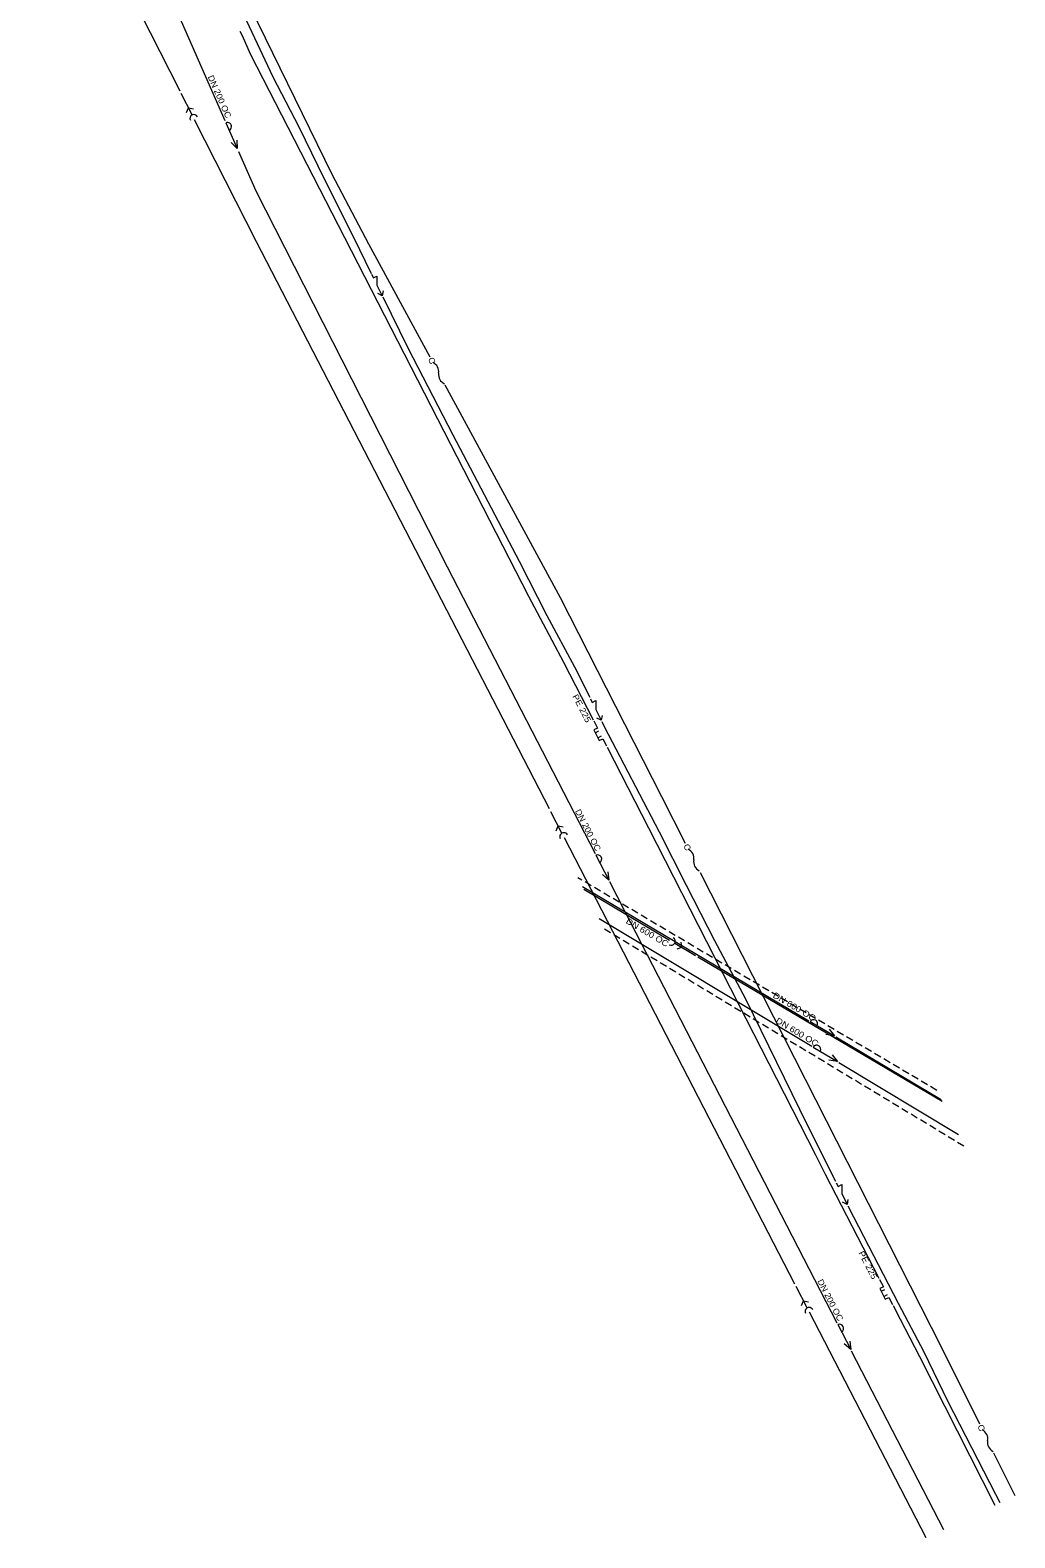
# Model space of a CAD drawing. Extents: x -601552 to -601367, y -1161450 to -1160710.
# Drawn here: x -601543.1 to -601420.6, y -1161449.9 to -1161262.3 of the extents above; entities that cross this region are included whole.
import ezdxf
from ezdxf.enums import TextEntityAlignment as Align

# ---------------------------------------------------------------- set-up
doc = ezdxf.new("R2010")
doc.units = 0
doc.header["$LTSCALE"] = 0.3
doc.linetypes.add('MEDIUM_DASHED', pattern=[4.5, 3, -1.5])
for name, color, linetype, lineweight in [('41', 7, 'Continuous', 13), ('50', 7, 'Continuous', 13), ('54', 7, 'Continuous', 13), ('56', 7, 'Continuous', 13), ('57', 7, 'Continuous', 13)]:
    doc.layers.add(name, color=color, linetype=linetype, lineweight=lineweight)

msp = doc.modelspace()

# ---------------------------------------------------------------- linework, layer by layer
at = {"layer": '41'}
for p, q in [((-601522.974, -1161272.877), (-601524.33, -1161270.201)), ((-601514.98, -1161288.65), (-601522.672, -1161273.473)), ((-601478.538, -1161359.202), (-601514.98, -1161288.65)), ((-601476.974, -1161362.231), (-601478.35, -1161359.565)), ((-601447.995, -1161418.332), (-601476.678, -1161362.804)), ((-601474.26, -1161369.184), (-601463.613, -1161375.538)), ((-601462.952, -1161375.934), (-601460.372, -1161377.463)), ((-601460.081, -1161377.635), (-601429.691, -1161395.588)), ((-601446.464, -1161421.298), (-601447.84, -1161418.633)), ((-601431.687, -1161449.906), (-601446.18, -1161421.846))]:
    msp.add_line(p, q, dxfattribs=at)
for points in [[(-601524.465, -1161269.936), (-601530.642, -1161257.748), (-601535.952, -1161244.775), (-601541.124, -1161228.471), (-601543.118, -1161218.344)], [(-601523.691, -1161272.568), (-601523.426, -1161271.985), (-601522.799, -1161272.116)], [(-601477.693, -1161361.927), (-601477.432, -1161361.342), (-601476.805, -1161361.468)], [(-601462.181, -1161375.809), (-601462.092, -1161376.443), (-601462.691, -1161376.67)], [(-601447.183, -1161420.994), (-601446.922, -1161420.41), (-601446.295, -1161420.536)]]:
    msp.add_lwpolyline(points, dxfattribs=at)
for centre, start, end in [((-601522.748, -1161273.3232), 26.87717, 206.87717), ((-601476.7441, -1161362.6748), 27.31763, 207.31763), ((-601463.3825, -1161375.6787), 239.34757, 59.34757), ((-601446.2341, -1161421.7424), 27.31763, 207.31763)]:
    msp.add_arc(centre, 0.5, start, end, dxfattribs=at)
at = {"layer": '50'}
msp.add_line((-601423.287, -1161439.316), (-601420.649, -1161444.638), dxfattribs=at)
for points in [[(-601524.04, -1161241.38), (-601521.24, -1161248.23), (-601520.37, -1161250), (-601505.61, -1161280.23)], [(-601505.61, -1161280.23), (-601501.04, -1161288.92), (-601493.427, -1161302.958)], [(-601491.527, -1161306.463), (-601477.19, -1161332.9), (-601464.6, -1161357.67), (-601461.658, -1161363.462)], [(-601459.803, -1161367.114), (-601429.78, -1161426.22), (-601425.061, -1161435.738)]]:
    msp.add_lwpolyline(points, dxfattribs=at)
for centre, start, end in [((-601493.5497, -1161304.8301), 351.60072, 65.34052), ((-601491.0765, -1161305.1953), 171.60072, 245.34052), ((-601461.8204, -1161365.3503), 350.05841, 63.79821), ((-601459.358, -1161365.7819), 170.05841, 243.79821), ((-601425.2601, -1161437.5876), 349.50224, 63.24203), ((-601422.802, -1161438.0431), 169.50224, 243.24203)]:
    msp.add_arc(centre, 1.25, start, end, dxfattribs=at)
at = {"layer": '54'}
for p, q in [((-601472.841, -1161349.734), (-601472.396, -1161349.506)), ((-601472.512, -1161350.376), (-601472.067, -1161350.148)), ((-601437.269, -1161419.233), (-601436.825, -1161419.004)), ((-601436.938, -1161419.874), (-601436.494, -1161419.644)), ((-601432.51, -1161427.34), (-601423.135, -1161445.826))]:
    msp.add_line(p, q, dxfattribs=at)
for points in [[(-601517.024, -1161262.44), (-601516.77, -1161263), (-601515.77, -1161265.3), (-601504.03, -1161288.15), (-601493.3, -1161309.08), (-601481.12, -1161332.74), (-601476.78, -1161340.95), (-601473.093, -1161348.147)], [(-601473.028, -1161348.273), (-601472.572, -1161349.163), (-601473.017, -1161349.391), (-601472.333, -1161350.726), (-601471.888, -1161350.498), (-601471.432, -1161351.388)], [(-601471.35, -1161351.547), (-601466.22, -1161361.56), (-601457.96, -1161377.75), (-601445.48, -1161402.19), (-601444.24, -1161404.65), (-601437.561, -1161417.579)], [(-601437.461, -1161417.772), (-601437.002, -1161418.661), (-601437.446, -1161418.89), (-601436.758, -1161420.223), (-601436.313, -1161419.993), (-601435.854, -1161420.882)], [(-601435.795, -1161420.997), (-601434.91, -1161422.71), (-601432.51, -1161427.34)]]:
    msp.add_lwpolyline(points, dxfattribs=at)
at = {"layer": '56'}
for p, q in [((-601518.771, -1161273.868), (-601517.363, -1161277.072)), ((-601472.758, -1161364.985), (-601471.154, -1161368.097)), ((-601474.429, -1161368.856), (-601446.289, -1161385.572)), ((-601472.363, -1161372.84), (-601445.916, -1161388.737)), ((-601446.101, -1161385.684), (-601443.091, -1161387.471)), ((-601445.718, -1161388.856), (-601442.718, -1161390.659)), ((-601442.91, -1161387.579), (-601429.801, -1161395.366)), ((-601442.556, -1161390.757), (-601427.658, -1161399.711)), ((-601442.668, -1161423.378), (-601441.065, -1161426.489)), ((-601440.985, -1161426.644), (-601429.528, -1161448.879))]:
    msp.add_line(p, q, dxfattribs=at)
at = {"layer": '56', "linetype": 'MEDIUM_DASHED'}
for p, q in [((-601430.36, -1161394.232), (-601474.983, -1161367.79)), ((-601471.689, -1161374.14), (-601426.944, -1161401.161))]:
    msp.add_line(p, q, dxfattribs=at)
at = {"layer": '56'}
for points in [[(-601537.46, -1161228.988), (-601536.54, -1161233.45), (-601518.908, -1161273.557)], [(-601517.422, -1161276.006), (-601517.363, -1161277.072), (-601518.108, -1161276.308)], [(-601517.21, -1161277.42), (-601515.06, -1161282.31), (-601491.25, -1161329.1), (-601472.863, -1161364.782)], [(-601471.279, -1161367.036), (-601471.154, -1161368.097), (-601471.946, -1161367.379)], [(-601471.076, -1161368.248), (-601469.147, -1161371.993), (-601467.069, -1161376.021), (-601442.785, -1161423.15)], [(-601443.76, -1161386.638), (-601443.091, -1161387.471), (-601444.143, -1161387.283)], [(-601443.382, -1161389.823), (-601442.718, -1161390.659), (-601443.768, -1161390.466)], [(-601441.189, -1161425.428), (-601441.065, -1161426.489), (-601441.856, -1161425.772)]]:
    msp.add_lwpolyline(points, dxfattribs=at)
for centre, start, end in [((-601518.5699, -1161274.326), 293.73141, 113.73141), ((-601472.5287, -1161365.4298), 297.26273, 117.26273), ((-601445.6708, -1161385.939), 329.28948, 149.28948), ((-601445.2893, -1161389.1138), 328.99072, 148.99072), ((-601442.4389, -1161423.822), 297.26077, 117.26077)]:
    msp.add_arc(centre, 0.5, start, end, dxfattribs=at)
at = {"layer": '57'}
for points in [[(-601526.307, -1161238.483), (-601526.246, -1161238.667), (-601523.573, -1161245.819), (-601519.028, -1161255.474), (-601515.871, -1161261.877), (-601512.935, -1161268.121), (-601509.702, -1161274.368), (-601506.556, -1161280.835), (-601502.916, -1161288.08), (-601500.69, -1161292.617)], [(-601500.65, -1161292.698), (-601500.43, -1161293.146), (-601499.981, -1161292.926), (-601499.99, -1161294.044), (-601499.329, -1161295.391)], [(-601499.212, -1161294.777), (-601499.329, -1161295.391), (-601499.886, -1161295.107)], [(-601499.266, -1161295.519), (-601496.152, -1161301.865), (-601490.546, -1161312.675), (-601482.288, -1161328.394), (-601478.866, -1161335.166), (-601475.412, -1161341.559), (-601473.523, -1161345.337)], [(-601473.435, -1161345.514), (-601473.212, -1161345.961), (-601472.764, -1161345.738), (-601472.764, -1161346.856), (-601472.094, -1161348.197)], [(-601471.982, -1161347.582), (-601472.094, -1161348.197), (-601472.653, -1161347.918)], [(-601472.014, -1161348.356), (-601471.706, -1161348.973), (-601464.893, -1161362.074), (-601461.529, -1161368.695), (-601458.007, -1161375.608), (-601454.167, -1161382.832), (-601447.418, -1161396.583), (-601444.514, -1161402.421), (-601442.964, -1161405.517)], [(-601442.856, -1161405.732), (-601442.632, -1161406.179), (-601442.185, -1161405.955), (-601442.185, -1161407.073), (-601441.513, -1161408.414)], [(-601441.401, -1161407.799), (-601441.513, -1161408.414), (-601442.072, -1161408.135)], [(-601441.425, -1161408.589), (-601440.733, -1161409.972), (-601435.141, -1161420.697), (-601431.95, -1161426.768), (-601429.023, -1161432.857), (-601423.055, -1161444.483), (-601422.509, -1161445.527)]]:
    msp.add_lwpolyline(points, dxfattribs=at)

# ---------------------------------------------------------------- texts
at = {"layer": '41', "width": 1.15}
msp.add_text('DN 600 OC', height=0.75, rotation=329.348, dxfattribs=at).set_placement((-601463.9804, -1161376.4281), align=Align.RIGHT)
at = {"layer": '50'}
for rotation, width, p in [(298.471, 1.15, (-601493.2837, -1161304.0105)), (296.928, 1.1, (-601461.5431, -1161364.5153)), (296.372, 1.1, (-601424.9791, -1161436.7469))]:
    msp.add_text('C', height=0.75, rotation=rotation, dxfattribs=dict(at, width=width)).set_placement(p, align=Align.RIGHT)
at = {"layer": '54', "width": 1.15}
for rotation, p in [(297.129, (-601473.9804, -1161348.565)), (297.321, (-601438.386, -1161417.8238))]:
    msp.add_text('PE 225', height=0.75, rotation=rotation, dxfattribs=at).set_placement(p, align=Align.RIGHT)
at = {"layer": '56', "width": 1.1}
for rotation, p in [(293.731, (-601518.756, -1161273.3582)), (297.263, (-601472.7613, -1161364.5594)), (297.261, (-601442.6215, -1161423.0315))]:
    msp.add_text('DN 200 OC', height=0.75, rotation=rotation, dxfattribs=at).set_placement(p, align=Align.RIGHT)
at = {"layer": '56', "width": 1.15}
for rotation, p in [(329.289, (-601450.827, -1161382.622)), (328.992, (-601450.466, -1161385.766))]:
    msp.add_text('DN 600 OC', height=0.75, rotation=rotation, dxfattribs=at).set_placement(p)

doc.saveas('drawing.dxf')
